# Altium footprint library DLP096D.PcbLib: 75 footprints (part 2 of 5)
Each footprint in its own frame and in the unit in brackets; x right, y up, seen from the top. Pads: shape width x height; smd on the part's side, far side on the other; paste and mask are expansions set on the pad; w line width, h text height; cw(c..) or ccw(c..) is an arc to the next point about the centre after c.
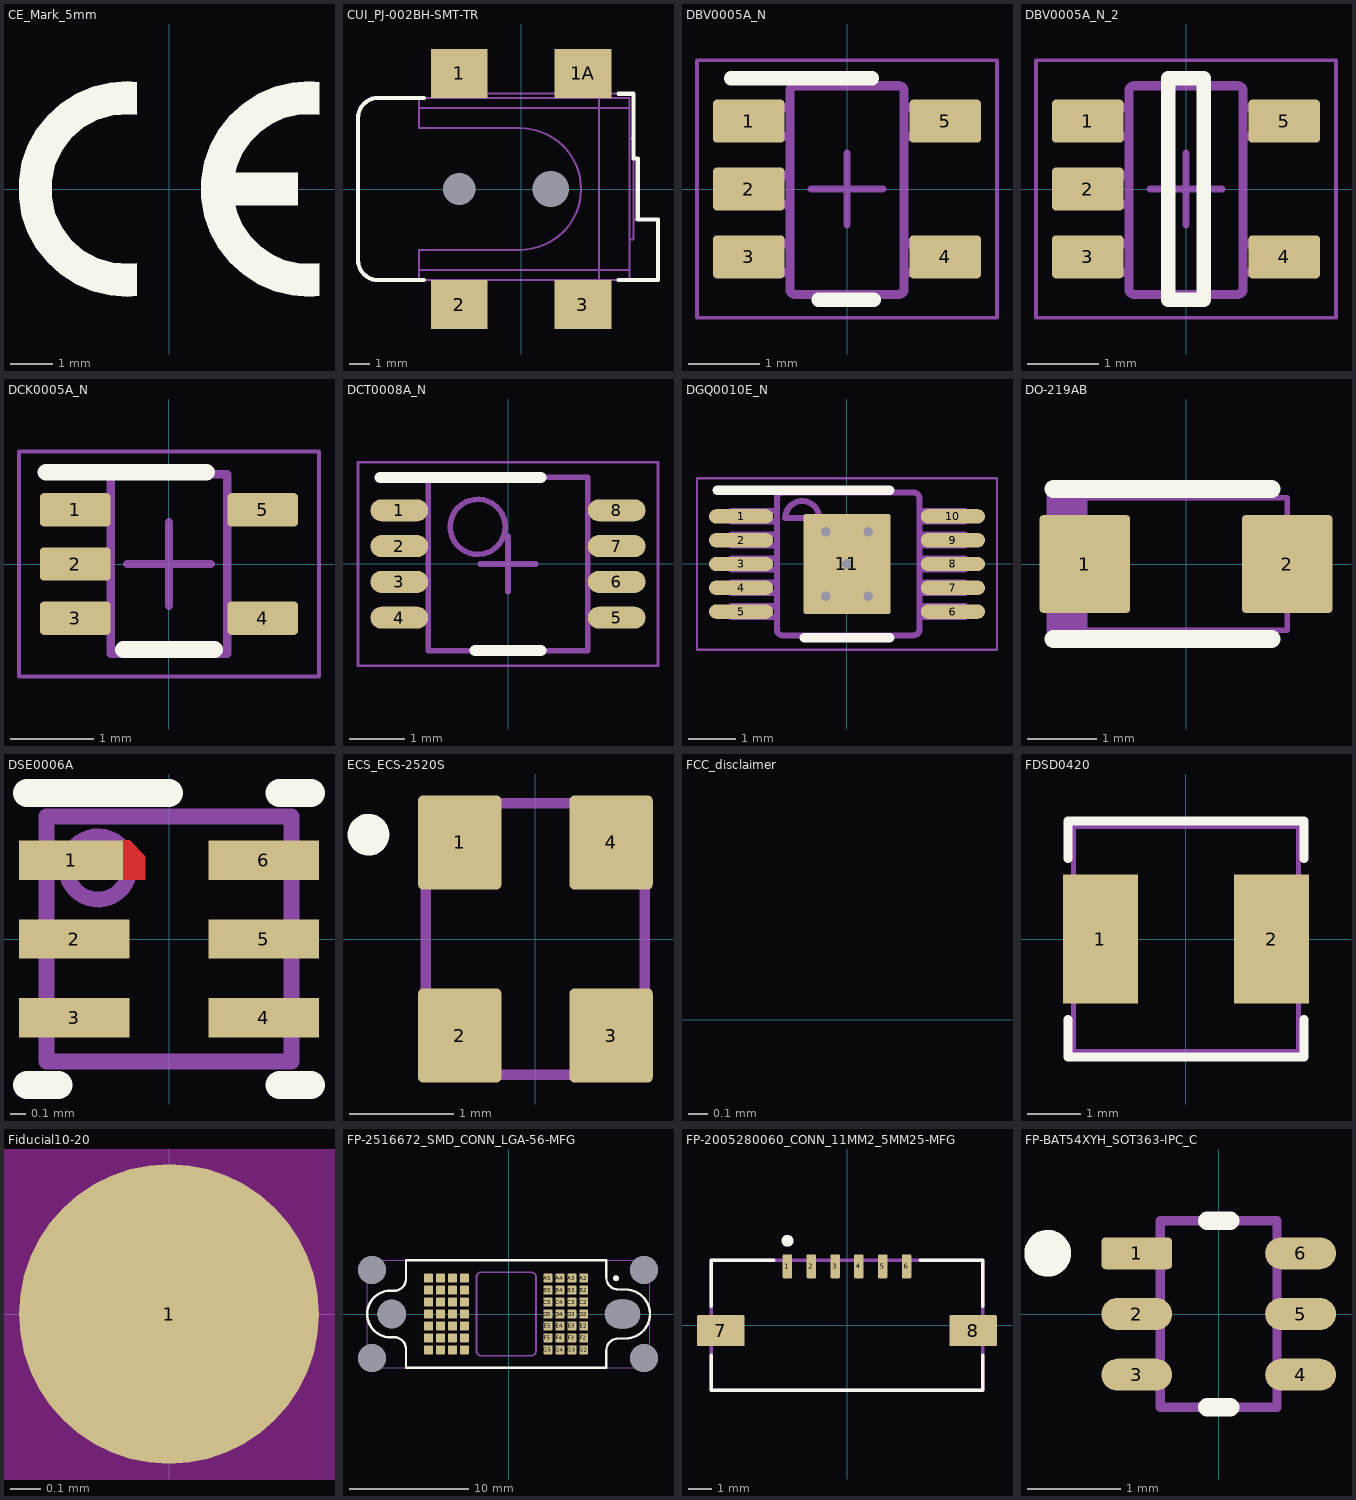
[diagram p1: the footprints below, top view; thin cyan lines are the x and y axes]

## CE_Mark_5mm [mm] "Minimum text height for CE Mark"
Top Overlay:
  region: 3.5,-1.732 3.337,-1.748 3.01,-1.733 2.691,-1.658 2.392,-1.525 2.123,-1.339 1.894,-1.106 1.712,-0.834 1.583,-0.533 1.541,-0.375 3,-0.375 3,0.375 1.541,0.375 1.583,0.533 1.712,0.834 1.894,1.106 2.123,1.339 2.392,1.525 2.691,1.658 3.01,1.733 3.337,1.748 3.5,1.732 3.5,2.487 3.292,2.508 2.874,2.48 2.467,2.383 2.081,2.22 1.728,1.994 1.418,1.714 1.158,1.385 0.957,1.018 0.82,0.622 0.75,0.209 0.75,-0.209 0.82,-0.622 0.957,-1.018 1.158,-1.385 1.418,-1.714 1.728,-1.994 2.081,-2.22 2.467,-2.383 2.874,-2.48 3.292,-2.508 3.5,-2.487
  region: -0.75,-2.487 -0.958,-2.508 -1.376,-2.48 -1.783,-2.383 -2.169,-2.22 -2.522,-1.994 -2.832,-1.714 -3.092,-1.385 -3.293,-1.018 -3.43,-0.622 -3.5,-0.209 -3.5,0.209 -3.43,0.622 -3.293,1.018 -3.092,1.385 -2.832,1.714 -2.522,1.994 -2.169,2.22 -1.783,2.383 -1.376,2.48 -0.958,2.508 -0.75,2.487 -0.75,1.732 -0.937,1.749 -1.31,1.722 -1.669,1.617 -1.998,1.438 -2.281,1.193 -2.505,0.893 -2.66,0.553 -2.74,0.187 -2.74,-0.187 -2.66,-0.553 -2.505,-0.893 -2.281,-1.193 -1.998,-1.438 -1.669,-1.617 -1.31,-1.722 -0.937,-1.749 -0.75,-1.732

## CUI_PJ-002BH-SMT-TR [mm] "Power Jack, 4-Leads, Body 14.8x9mm, R/A, SMT"
height 11.23
pads (6):
  rect 2.8x2.4 smd: 1(-3.05,5.7) 1A(3.05,5.7) 2(-3.05,-5.7) 3(3.05,-5.7)
  round 0 hole 1.6 unplated: 4(-3.05,0)
  round 0 hole 1.8 unplated: 5(1.45,0)
Top Overlay:
  lines w0.2: -4.8,-4.5 -7.05,-4.5 cw(c-7.05,-3.5) -8.05,-3.5 -8.05,3.5 cw(c-7.05,3.5) -7.05,4.5 -4.8,4.5 ; 4.8,-4.5 6.75,-4.5 6.75,-1.5 5.75,-1.5 5.75,1.5 5.55,1.5 5.55,2.5 5.55,4.7 4.8,4.7
Mechanical 5:
  lines w0.1: -5.05,-4 3.85,-4 ; -5.05,4 3.85,4 ; -4.4,4.5 -4.4,5 -3.1,5 -3.1,4.5 ; -3.8,-4.5 -3.8,-5 ; -3.8,5 -3.8,6.3 -2.3,6.3 -2.3,4.7 ; -3.1,4.7 5.55,4.7 5.55,2.5 ; -2.3,-4.5 -2.3,-5 ; 1.8,-4.5 1.8,-5 3.8,-5 ; 2.3,-5 2.3,-6.3 3.8,-6.3 3.8,-5 ; 2.3,4.7 2.3,6.3 3.8,6.3 3.8,4.7 ; 3.8,-4.5 3.8,-5 ; 5.35,-2.5 5.55,-2.5 5.55,2.5 ; 5.35,2.5 5.55,2.5 ; 5.55,-1.5 5.75,-1.5 ; 5.55,1.5 5.75,1.5 5.75,-1.5 ; -5.05,-4.5 -7.05,-4.5 cw(c-7.05,-3.5) -8.05,-3.5 -8.05,3.5 cw(c-7.05,3.5) -7.05,4.5 -5.05,4.5 ; -5.05,-4.5 -5.05,-4.3 -5.05,-3 -0.05,-3 ccw(c-0.05,0) 2.95,0 ccw(c-0.05,0) -0.05,3 -5.05,3 -5.05,4.3 -5.05,4.5 ; -5.05,-4.5 3.85,-4.5 ; -5.05,4.5 3.85,4.5 ; -3.8,-5 -2.3,-5 ; -3.8,-5 -3.8,-6.3 -2.3,-6.3 -2.3,-5 ; 3.85,-4.5 3.85,-4 ; 3.85,-4.5 5.35,-4.5 ; 3.85,-4.5 3.85,-4 ; 3.85,-4 3.85,4 ; 3.85,-4 5.35,-4 ; 3.85,-4 3.85,4 ; 3.85,4 5.35,4 ; 3.85,4 3.85,4.5 ; 3.85,4 3.85,4.5 ; 3.85,4.5 5.35,4.5 5.35,4 ; 5.35,-4.5 6.75,-4.5 6.75,-1.5 5.75,-1.5 ; 5.35,-4.5 5.35,-4 ; 5.35,-4 5.35,4
  text ".Designator" at -1.524,-0.508 h1.02
3D body "pj-002bh-smt.stp": height 11.2, standoff -1, extent -8.05,-6.3 6.75,6.3

## DBV0005A_N [mm] "SOT23, 5-Leads, Body 2.9x1.6mm, Pitch 0.95mm, Lead Span 2.8mm, IPC Medium Density"
height 1.45
pads (5):
  rrect17% 1x0.6 smd: 1(-1.375,0.95) 2(-1.375,0) 3(-1.375,-0.95) 4(1.375,-0.95) 5(1.375,0.95)
Top Overlay:
  lines w0.2: -1.625,1.55 0.35,1.55 ; -0.4,-1.55 0.375,-1.55
Mechanical 5:
  lines w0.127: -0.801,1.371 cw(c-0.725,1.37) -0.725,1.446 ; -0.801,1.37 -0.801,1.371 ; -0.801,1.37 -0.801,-1.399 -0.801,-1.4 ccw(c-0.725,-1.399) -0.725,-1.475 ; -0.725,-1.475 0.723,-1.475 0.724,-1.475 ccw(c0.723,-1.399) 0.799,-1.4 0.799,-1.399 0.799,1.37 ; -0.725,-1.475 -0.725,-1.475 ; -0.725,1.446 -0.725,1.446 ; -0.725,1.446 0.723,1.446 0.724,1.446 cw(c0.723,1.37) 0.799,1.371 ; 0.799,1.37 0.799,1.371 ; -1.423,-1.167 -1.423,-0.767 -1.199,-0.767 -1.105,-0.767 -1.088,-0.767 -0.835,-0.767 -0.801,-0.767 -0.801,-1.167 -0.835,-1.167 -1.088,-1.167 -1.105,-1.167 -1.199,-1.167 -1.423,-1.167 ; -1.423,-0.215 -1.423,0.186 -1.199,0.186 -1.105,0.186 -1.088,0.186 -0.835,0.186 -0.801,0.186 -0.801,-0.215 -0.835,-0.215 -1.088,-0.215 -1.105,-0.215 -1.199,-0.215 -1.423,-0.215 ; -1.423,0.738 -1.423,1.138 -1.199,1.138 -1.105,1.138 -1.088,1.138 -0.835,1.138 -0.801,1.138 -0.801,0.738 -0.835,0.738 -1.088,0.738 -1.105,0.738 -1.199,0.738 -1.423,0.738 ; 0.799,-1.167 0.834,-1.167 1.087,-1.167 1.103,-1.167 1.198,-1.167 1.422,-1.167 1.422,-0.767 1.198,-0.767 1.103,-0.767 1.087,-0.767 0.834,-0.767 0.799,-0.767 0.799,-1.167 ; 0.799,0.738 0.834,0.738 1.087,0.738 1.103,0.738 1.198,0.738 1.422,0.738 1.422,1.138 1.198,1.138 1.103,1.138 1.087,1.138 0.834,1.138 0.799,1.138 0.799,0.738
  text ".Designator" at -0.25,0.95 h0.51
Mechanical 15:
  lines w0.05: -2.1,-1.8 -2.1,1.8 2.1,1.8 2.1,-1.8 -2.1,-1.8
  lines w0.1: -0.5,0 0.5,0 ; 0,-0.5 0,0.5
3D body "DBV0005A.stp": height 1.09, standoff 0, extent -1.422,-1.461 1.423,1.46

## DBV0005A_N_2 [mm]
pads (5):
  rrect17% 1x0.6 smd: 1(-1.375,0.95) 2(-1.375,0) 3(-1.375,-0.95) 4(1.375,-0.95) 5(1.375,0.95)
Top Overlay:
  lines w0.2: -0.25,-1.55 0.25,-1.55 0.25,1.55 -0.25,1.55 -0.25,-1.55
Mechanical 5:
  lines w0.127: -0.801,1.371 cw(c-0.725,1.37) -0.725,1.446 ; -0.801,1.37 -0.801,-1.399 -0.801,-1.4 ccw(c-0.725,-1.399) -0.725,-1.475 ; -0.801,1.37 -0.801,1.371 ; -0.725,-1.475 -0.725,-1.475 ; -0.725,-1.475 0.723,-1.475 0.724,-1.475 ccw(c0.723,-1.399) 0.799,-1.4 0.799,-1.399 0.799,1.37 ; -0.725,1.446 0.723,1.446 0.724,1.446 cw(c0.723,1.37) 0.799,1.371 ; -0.725,1.446 -0.725,1.446 ; 0.799,1.37 0.799,1.371 ; -1.423,-1.167 -1.199,-1.167 -1.105,-1.167 -1.088,-1.167 -0.835,-1.167 -0.801,-1.167 -0.801,-0.767 -0.835,-0.767 -1.088,-0.767 -1.105,-0.767 -1.199,-0.767 -1.423,-0.767 -1.423,-1.167 ; -1.423,-0.215 -1.199,-0.215 -1.105,-0.215 -1.088,-0.215 -0.835,-0.215 -0.801,-0.215 -0.801,0.186 -0.835,0.186 -1.088,0.186 -1.105,0.186 -1.199,0.186 -1.423,0.186 -1.423,-0.215 ; -1.423,0.738 -1.199,0.738 -1.105,0.738 -1.088,0.738 -0.835,0.738 -0.801,0.738 -0.801,1.138 -0.835,1.138 -1.088,1.138 -1.105,1.138 -1.199,1.138 -1.423,1.138 -1.423,0.738 ; 0.799,-1.167 0.799,-0.767 0.834,-0.767 1.087,-0.767 1.103,-0.767 1.198,-0.767 1.422,-0.767 1.422,-1.167 1.198,-1.167 1.103,-1.167 1.087,-1.167 0.834,-1.167 0.799,-1.167 ; 0.799,0.738 0.799,1.138 0.834,1.138 1.087,1.138 1.103,1.138 1.198,1.138 1.422,1.138 1.422,0.738 1.198,0.738 1.103,0.738 1.087,0.738 0.834,0.738 0.799,0.738
  text ".Designator" at -0.25,0.95 h0.51
Mechanical 15:
  lines w0.05: -2.1,-1.8 2.1,-1.8 2.1,1.8 -2.1,1.8 -2.1,-1.8
  lines w0.1: -0.5,0 0.5,0 ; 0,-0.5 0,0.5
3D body "DBV0005A.stp": height 1.09, standoff 0, extent -1.422,-1.461 1.423,1.46

## DCK0005A_N [mm] "SOT353, 5-Leads, Body 2x1.3mm, Pitch 0.65mm, Lead Span 2.1mm, IPC Medium Density"
height 1.1
pads (5):
  rrect25% 0.85x0.4 smd: 1(-1.125,0.65) 2(-1.125,0) 3(-1.125,-0.65) 4(1.125,-0.65) 5(1.125,0.65)
Top Overlay:
  lines w0.2: -1.475,1.1 0.45,1.1 ; -0.55,-1.025 0.55,-1.025
Mechanical 5:
  lines w0.1: -0.7,-1.075 -0.7,1.075 0.7,1.075 0.7,-1.075 -0.7,-1.075
  lines w0.127: -0.865,0.762 -0.853,0.762 ; -0.711,-0.763 -0.853,-0.763 -0.865,-0.763 -0.959,-0.763 -1.143,-0.763 -1.143,-0.538 -0.959,-0.538 -0.865,-0.538 -0.853,-0.538 -0.711,-0.538 ; -0.711,-0.113 -0.853,-0.113 -0.865,-0.113 -0.959,-0.113 -1.143,-0.113 -1.143,0.112 -0.959,0.112 -0.865,0.112 -0.853,0.112 -0.711,0.112 ; -0.711,0.537 -0.853,0.537 -0.865,0.537 -0.959,0.537 -1.143,0.537 -1.143,0.762 -0.959,0.762 -0.711,0.762 ; 0.711,-0.763 0.847,-0.763 0.859,-0.763 0.953,-0.763 1.137,-0.763 1.137,-0.538 0.953,-0.538 0.859,-0.538 0.847,-0.538 0.711,-0.538 ; 0.711,0.537 0.847,0.537 0.859,0.537 0.953,0.537 1.137,0.537 1.137,0.762 0.953,0.762 0.859,0.762 0.847,0.762 0.711,0.762
  text ".Designator" at -0.254,0.914 h0.51
Mechanical 15:
  lines w0.05: -1.8,-1.35 -1.8,1.35 1.8,1.35 1.8,-1.35 -1.8,-1.35
  lines w0.1: -0.5,0 0.5,0 ; 0,-0.5 0,0.5
3D body "DCK0005A.stp": height 0.95, standoff 0, extent -1.14,-1 1.14,1

## DCT0008A_N [mm] "TSOP, 8-Leads, Body 3x2.8mm, Pitch 0.65mm, IPC Medium Density"
height 1.3
pads (8):
  oval 1.05x0.4 smd: 1(-1.975,0.975) 2(-1.975,0.325) 3(-1.975,-0.325) 4(-1.975,-0.975) 5(1.975,-0.975) 6(1.975,-0.325) 7(1.975,0.325) 8(1.975,0.975)
Top Overlay:
  lines w0.2: -2.325,1.575 0.6,1.575 ; -0.6,-1.575 0.6,-1.575
Mechanical 5:
  circle w0.1: c-0.55,0.675 r0.5
  lines w0.1: -1.45,-1.575 1.45,-1.575 1.45,1.575 -1.45,1.575 -1.45,-1.575
  text ".Designator" at -1.016,-0.889 h0.51
Mechanical 15:
  lines w0.05: -2.725,-1.85 -2.725,1.85 2.725,1.85 2.725,-1.85 -2.725,-1.85
  lines w0.1: -0.5,0 0.5,0 ; 0,-0.5 0,0.5
3D body "DCT0008A.stp": height 1.3, standoff 0, extent -2.011,-1.475 2.011,1.475

## DGQ0010E_N [mm] "TSSOP, 10-Leads, Body 3x3mm, Pitch 0.5mm, Thermal Pad 1.83x2.1mm, IPC Medium Density"
height 1.1
pads (11):
  rrect100% 1.35x0.3 smd: 1(-2.225,1) 2(-2.225,0.5) 3(-2.225,0) 4(-2.225,-0.5) 5(-2.225,-1) 6(2.225,-1) 7(2.225,-0.5) 8(2.225,0) 9(2.225,0.5) 10(2.225,1)
  rrect5% 1.83x2.1 smd: 11(0,0)
via -0.45,0.675 diameter 0.5 hole 0.2
via -0.45,-0.675 diameter 0.5 hole 0.2
via 0.45,-0.675 diameter 0.5 hole 0.2
via 0.45,0.675 diameter 0.5 hole 0.2
via 0,0 diameter 0.5 hole 0.2
Top Overlay:
  lines w0.2: -2.725,1.55 0.9,1.55 ; -0.9,-1.55 0.9,-1.55
Mechanical 5:
  lines w0.127: -2.427,-1.114 -2.187,-1.114 -2.067,-1.114 -2.064,-1.114 -1.76,-1.114 -1.474,-1.114 -1.474,-0.885 -1.76,-0.885 -2.064,-0.885 -2.067,-0.885 -2.187,-0.885 -2.427,-0.885 -2.427,-1.114 ; -2.427,-0.613 -2.187,-0.613 -2.067,-0.613 -2.064,-0.613 -1.76,-0.613 -1.474,-0.613 -1.474,-0.385 -1.76,-0.385 -2.064,-0.385 -2.067,-0.385 -2.187,-0.385 -2.427,-0.385 -2.427,-0.613 ; -2.427,-0.113 -2.187,-0.113 -2.067,-0.113 -2.064,-0.113 -1.76,-0.113 -1.474,-0.113 -1.474,0.116 -1.76,0.116 -2.064,0.116 -2.067,0.116 -2.187,0.116 -2.427,0.116 -2.427,-0.113 ; -2.427,0.388 -2.187,0.388 -2.067,0.388 -2.064,0.388 -1.76,0.388 -1.474,0.388 -1.474,0.616 -1.76,0.616 -2.064,0.616 -2.067,0.616 -2.187,0.616 -2.427,0.616 -2.427,0.388 ; -2.427,0.888 -2.187,0.888 -2.067,0.888 -2.064,0.888 -1.76,0.888 -1.474,0.888 -1.474,1.116 -1.76,1.116 -2.064,1.116 -2.067,1.116 -2.187,1.116 -2.427,1.116 -2.427,0.888 ; -1.474,-1.373 ccw(c-1.347,-1.37) -1.35,-1.497 -1.347,-1.497 1.396,-1.497 1.399,-1.497 ccw(c1.396,-1.37) 1.523,-1.373 1.523,-1.37 1.523,1.373 1.523,1.376 ccw(c1.396,1.373) 1.399,1.5 1.396,1.5 -1.347,1.5 -1.35,1.5 ccw(c-1.347,1.373) -1.474,1.376 -1.474,1.373 -1.474,-1.37 -1.474,-1.373 ; -1.296,0.967 cw(c-0.941,0.967) -0.585,0.967 -1.296,0.967 ; 1.523,-1.114 1.523,-0.885 1.809,-0.885 2.113,-0.885 2.116,-0.885 2.236,-0.885 2.475,-0.885 2.475,-1.114 2.236,-1.114 2.116,-1.114 2.113,-1.114 1.809,-1.114 1.523,-1.114 ; 1.523,-0.613 1.523,-0.385 1.809,-0.385 2.113,-0.385 2.116,-0.385 2.236,-0.385 2.475,-0.385 2.475,-0.613 2.236,-0.613 2.116,-0.613 2.113,-0.613 1.809,-0.613 1.523,-0.613 ; 1.523,-0.113 1.523,0.116 1.809,0.116 2.113,0.116 2.116,0.116 2.236,0.116 2.475,0.116 2.475,-0.113 2.236,-0.113 2.116,-0.113 2.113,-0.113 1.809,-0.113 1.523,-0.113 ; 1.523,0.388 1.523,0.616 1.809,0.616 2.113,0.616 2.116,0.616 2.236,0.616 2.475,0.616 2.475,0.388 2.236,0.388 2.116,0.388 2.113,0.388 1.809,0.388 1.523,0.388 ; 1.523,0.888 1.523,1.116 1.809,1.116 2.113,1.116 2.116,1.116 2.236,1.116 2.475,1.116 2.475,0.888 2.236,0.888 2.116,0.888 2.113,0.888 1.809,0.888 1.523,0.888
  text ".Designator" at -0.975,-0.25 h0.51
Mechanical 15:
  lines w0.05: -3.15,-1.8 -3.15,1.8 3.15,1.8 3.15,-1.8 -3.15,-1.8
  lines w0.1: -0.5,0 0.5,0 ; 0,-0.5 0,0.5
3D body "DGQ0010E.stp": height 0.95, standoff 0, extent -2.46,-1.5 2.46,1.5

## DO-219AB [mm] "Vishay Semiconductor"
height 1.08
pads (2):
  rrect8% 1.3x1.4 smd: 1(-1.45,0) 2(1.45,0)
Top Overlay:
  lines w0.254: -1.9,-1.075 1.225,-1.075 ; -1.9,1.075 1.225,1.075
Mechanical 5:
  rectangle: -2,-0.975 -1.472,0.991
  lines w0.08: -1.45,-0.95 1.45,-0.95 1.45,0.95 -1.45,0.95 -1.45,-0.95
  text ".Designator" at -1.2,-0.275 h0.7
3D body "DO-219A.stp": height 1.09, standoff 0.01, extent -1.95,-0.95 1.95,0.95

## DSE0006A [mm] "TI recommended land pattern"
height 0.8
pads (6):
  rect 0.66x0.25 smd: 1(-0.62,0.5)
  rect 0.7x0.25 smd: 2(-0.6,0) 3(-0.6,-0.5) 4(0.6,-0.5) 5(0.6,0) 6(0.6,0.5)
Top Layer:
  region: -0.3,0.625 -0.25,0.625 -0.15,0.525 -0.15,0.375 -0.3,0.375
Top Overlay:
  lines w0.178: -0.9,-0.925 -0.7,-0.925 ; -0.9,0.925 0,0.925 ; 0.7,-0.925 0.9,-0.925 ; 0.7,0.925 0.9,0.925
Mechanical 5:
  circle w0.1: c-0.45,0.45 r0.2
  lines w0.1: -0.775,-0.775 -0.775,0.775 0.775,0.775 0.775,-0.775 -0.775,-0.775
  text ".Designator" at -0.575,-0.325 h0.3
3D body: height 0.8, standoff 0, extent -0.774,-0.774 0.774,0.774
3D body: height 0.8, standoff 0.76, extent -0.548,0.362 -0.352,0.558

## ECS_ECS-2520S [mm] "SMD, 4-Leads, Body 2x2.5mm"
height 1
pads (4):
  rrect12% 0.8x0.9 smd: 1(-0.725,0.925) 2(-0.725,-0.925) 3(0.725,-0.925) 4(0.725,0.925)
Top Overlay:
  circle w0.2: c-1.6,1 r0.1
Mechanical 5:
  circle w0.1: c-0.6,0.8 r0.141
  lines w0.1: -1.05,-1.3 -1.05,1.3 1.05,1.3 1.05,-1.3 -1.05,-1.3
  text ".Designator" at -0.9,-0.2 h0.45
3D body: height 1, standoff 0, extent -1.049,-1.299 1.049,1.299
3D body: height 1, standoff 0.6, extent -0.741,0.659 -0.459,0.941

## FCC_disclaimer [mm]
Top Overlay:
  text "For evaluation only; not FCC approved for resale." at -15.928,-0.353 h1.52

## FDSD0420 [mm] "SMD, 2-Leads, Body 4.2x4.2mm"
height 2
pads (2):
  rect 1.4x2.4 smd: 1(-1.6,0) 2(1.6,0)
Top Overlay:
  lines w0.17: -2.2,-1.5 -2.2,-2.2 2.2,-2.2 2.2,-1.5 ; -2.2,1.5 -2.2,2.2 2.2,2.2 2.2,1.5
Mechanical 5:
  lines w0.1: -2.1,-2.1 2.1,-2.1 2.1,2.1 -2.1,2.1 -2.1,-2.1
  text ".Designator" at -1.524,-0.508 h1.02
3D body: height 2, standoff 0, extent -2.099,-2.099 2.099,2.099

## Fiducial10-20 [mm]
pads (1):
  round 1 smd mask+0.5: 1(0,0)
Top Layer keep-out:
  circle w1.178: c0,0 r0.5

## FP-2516672_SMD_CONN_LGA-56-MFG [mm]
pads (62):
  rrect13% 0.75x0.75 smd paste-1000 mask+0: A2(6.3,3) A3(5.3,3) A4(4.3,3) A5(3.3,3) A12(-3.7,3) A13(-4.7,3) A14(-5.7,3) A15(-6.7,3) B2(6.3,2) B3(5.3,2) B4(4.3,2) B5(3.3,2) B12(-3.7,2) B13(-4.7,2) B14(-5.7,2) B15(-6.7,2) C2(6.3,1) C3(5.3,1) C4(4.3,1) C5(3.3,1) C12(-3.7,1) C13(-4.7,1) C14(-5.7,1) C15(-6.7,1) D2(6.3,0) D3(5.3,0) D4(4.3,0) D5(3.3,0) D12(-3.7,0) D13(-4.7,0) D14(-5.7,0) D15(-6.7,0) E2(6.3,-1) E3(5.3,-1) E4(4.3,-1) E5(3.3,-1) E12(-3.7,-1) E13(-4.7,-1) E14(-5.7,-1) E15(-6.7,-1) F2(6.3,-2) F3(5.3,-2) F4(4.3,-2) F5(3.3,-2) F12(-3.7,-2) F13(-4.7,-2) F14(-5.7,-2) F15(-6.7,-2) G2(6.3,-3) G3(5.3,-3) G4(4.3,-3) G5(3.3,-3) G12(-3.7,-3) G13(-4.7,-3) G14(-5.7,-3) G15(-6.7,-3)
  round 2.35 hole 2.35 unplated paste-1000 mask+0: ""(-11.45,-3.7) ""(-11.45,3.7) ""(11.35,-3.7) ""(11.35,3.7)
  round 2.4 hole 2.4 unplated paste-1000 mask+0: ""(-9.8,0)
  rrect100% 2.95x2.4 hole 2.4 slot 2.95 at 0 deg unplated paste-1000 mask+0: ""(9.55,0)
Top Overlay:
  circle w0.25: c9,3 r0.125
  lines w0.2: -9.9,-1.95 cw(c-9.906,0) -9.9,1.95 -9.6,1.95 ccw(c-9.6,2.95) -8.6,2.95 -8.6,4.5 8.2,4.5 8.2,3.05 ccw(c9.2,3.05) 9.2,2.05 9.8,2.05 cw(c9.807,0) 9.8,-2.05 9.2,-2.05 ccw(c9.2,-3.05) 8.2,-3.05 8.2,-4.5 -8.6,-4.5 -8.6,-2.95 ccw(c-9.6,-2.95) -9.6,-1.95 -9.9,-1.95
Mechanical 2:
  lines w0.15: -2.7,-3.1 ccw(c-2.3,-3.1) -2.3,-3.5 1.9,-3.5 ccw(c1.9,-3.1) 2.3,-3.1 2.3,3.1 ccw(c1.9,3.1) 1.9,3.5 -2.3,3.5 ccw(c-2.3,3.1) -2.7,3.1 -2.7,-3.1
Mechanical 5:
  lines w0.1: -11.85,-4.5 -11.85,4.5 11.85,4.5 11.85,-4.5 -11.85,-4.5
  text ".Designator" at -0.05,0 h0.5
3D body "Conn_2516672_SMD_CONN_LGA_56.stp": height 1.4, standoff 0, extent -11.725,-4.5 11.975,4.5

## FP-2005280060_CONN_11MM2_5MM25-MFG [mm]
pads (8):
  rrect25% 0.4x1 smd paste+0 mask+0: 1(-2.5,2.475) 2(-1.5,2.475) 3(-0.5,2.475) 4(0.5,2.475) 5(1.5,2.475) 6(2.5,2.475)
  rrect8% 2x1.3 smd paste+0 mask+0: 7(-5.3,-0.225) 8(5.3,-0.225)
Top Overlay:
  circle w0.25: c-2.5,3.55 r0.125
  lines w0.15: -5.7,-1.25 -5.7,-2.725 5.7,-2.725 5.7,-1.25 ; -5.7,0.8 -5.7,2.725 -3.075,2.725 ; 3.075,2.725 5.7,2.725 5.7,0.8
Mechanical 5:
  lines w0.15: -5.7,-2.725 5.7,-2.725 5.7,2.725 -5.7,2.725 -5.7,-2.725
  text ".Designator" at 0,0.125 h0.5
3D body "Conn_2005280060_CONN_11MM2_5MM25.STEP": height 0.25, standoff 0, extent -6.4,-2.825 6.4,3.075

## FP-BAT54XYH_SOT363-IPC_C [mm]
pads (6):
  rrect29% 0.759x0.342 smd paste+0 mask+0: 1(-0.877,0.65)
  rrect100% 0.759x0.342 smd paste+0 mask+0: 2(-0.877,0) 3(-0.877,-0.65) 4(0.877,-0.65) 5(0.877,0) 6(0.877,0.65)
Top Overlay:
  circle w0.25: c-1.831,0.65 r0.125
  lines w0.2: -0.122,-1 0.122,-1 ; -0.122,1 0.122,1
Mechanical 5:
  lines w0.1: -0.625,-1 0.625,-1 0.625,1 -0.625,1 -0.625,-1
  text ".Designator" at 0,0 h0.5
3D body "Diode_BAT54XYH_SOT363.STEP": height 0.25, standoff 0, extent -1.356,-1.1 1.356,1.1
